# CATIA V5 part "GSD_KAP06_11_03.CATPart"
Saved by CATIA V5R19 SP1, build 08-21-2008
Part number: GSD_BLEND_04
Definition: Beispielmodell für die Funktion Übergang / Blend - Automatische Verbindung.
Description: CATIA V5 Flächenmodellierung  Copyright (c) 2009 Maik Hertha IT Consultants
Bounding box of the stored display mesh (mm): x -164.511 to 102.98, y -20 to 224.611, z -30.362 to 44.999
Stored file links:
  \GSD_BUCH_UEBUNG\GSD_KAP06_11_03.CATPart
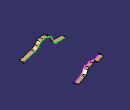
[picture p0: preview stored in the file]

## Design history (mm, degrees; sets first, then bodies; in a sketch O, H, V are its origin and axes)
AxisSystem1: origin (0, 0, 0), X (1, 0, 0), Y (0, 1, 0), Z (0, 0, 1)
Set1
  Sketch1 on ZX plane of AxisSystem1, origin (0, 0, 0), H (0, 0, 1), V (1, 0, 0)
    line L1 (-7.7811, 102.9804) -> (10.5771, 41.6998)
    arc A1 centre (44.1049, 51.744) radius 35 from (10.5771, 41.6998) to (24.809, 22.5435) ccw
    arc A2 centre (0, -15) radius 45 from (24.809, 22.5435) to (37.9923, 9.116) cw
    point P5 (0, -15)
    arc A3 centre (0, -15) radius 45 from (33.7014, -44.8197) to (4.0909, -59.8137) cw
    point P7 (0, -15)
    line L2 (-5, -69.7723) -> (-5, -121.1063)
    construction line L3 (70.2481, 0) -> (-64.8444, 0)
    point P8 (70.2481, 0)
    construction line L4 (0, 45.8622) -> (0, -41.9018)
    point P10 (0, 45.8622)
    curve C1
    arc A4 centre (5, -69.7723) radius 10 from (4.0909, -59.8137) to (-5, -69.7723) ccw
    arc A5 centre (0, -15) radius 45 from (37.9923, 9.116) to (43.6257, -3.9639) cw
    arc A6 centre (0, -15) radius 45 from (41.4452, -32.5298) to (33.7014, -44.8197) cw
    arc A7 centre (0, -15) radius 45 from (43.6257, -3.9639) to (41.4452, -32.5298) cw
    radius A3 = 45
    distance L4 L2 = 5
    distance P5 L3 = 15
    radius A4 = 10
    radius A1 = 35
    tangency: A1 L1, A2 A1, A3 A2, A4 L2, A4 A3
    vertical: L2 V, L4 V
    coincidence: P7 P5, P8 H, P10 V, P5 L4, A2 A5, A5 A6, A5 A7
    horizontal: L3 H
  Sketch2 on XY plane of AxisSystem1, origin (0, 0, 0), H (1, 0, 0), V (0, 1, 0)
    spline S1 through (63.5198, 0.6594) (52.4947, 108.5036) (27.7222, 201.6743)
    construction line L1 (63.5198, -33.9776) -> (63.5198, 23.4257)
    curve C1
    vertical: L1 V
  Plane1: type Normal, Curve Sketch2.C1, RefPoint {point type OnCurve, Support Sketch2.C1, Ratio 1}
  Sketch3 on Plane1, origin (27.7222, 201.6743, 0), H (-0.9497, -0.3131, 0), V (0, 0, 1)
    line L1 (-12.5925, -30.3622) -> (43.5645, -30.3622)
    line L2 (50.3453, -27.7121) -> (65.7944, -13.4594)
    line L3 (77.0077, -9.5205) -> (111.3244, -11.9105)
    line L4 (134.514, -21.3899) -> (139.6722, -25.7927)
    line L5 (149.4105, -29.3837) -> (195.8144, -29.3837)
    curve C1
    arc A1 centre (43.5645, -20.3622) radius 10 from (43.5645, -30.3622) to (50.3453, -27.7121) ccw
    arc A2 centre (75.9655, -24.4842) radius 15 from (65.7944, -13.4594) to (77.0077, -9.5205) cw
    arc A3 centre (108.5452, -51.8139) radius 40 from (111.3244, -11.9105) to (134.514, -21.3899) cw
    arc A4 centre (149.4105, -14.3837) radius 15 from (139.6722, -25.7927) to (149.4105, -29.3837) ccw
    radius A1 = 10
    radius A4 = 15
    radius A3 = 40
    radius A2 = 15
    horizontal: L1 H, L5 H
    tangency: A1 L1, A1 L2, A2 L2, A2 L3, A3 L3, A3 L4, A4 L4, A4 L5
  Extrude1: Lim1 20, Lim2 0, Element1 Sketch3.C1, Direction Plane1
  Extrude2: Lim1 20, Lim2 0, Element1 Sketch1.C1, Direction zx-plane
Body1 (main body)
